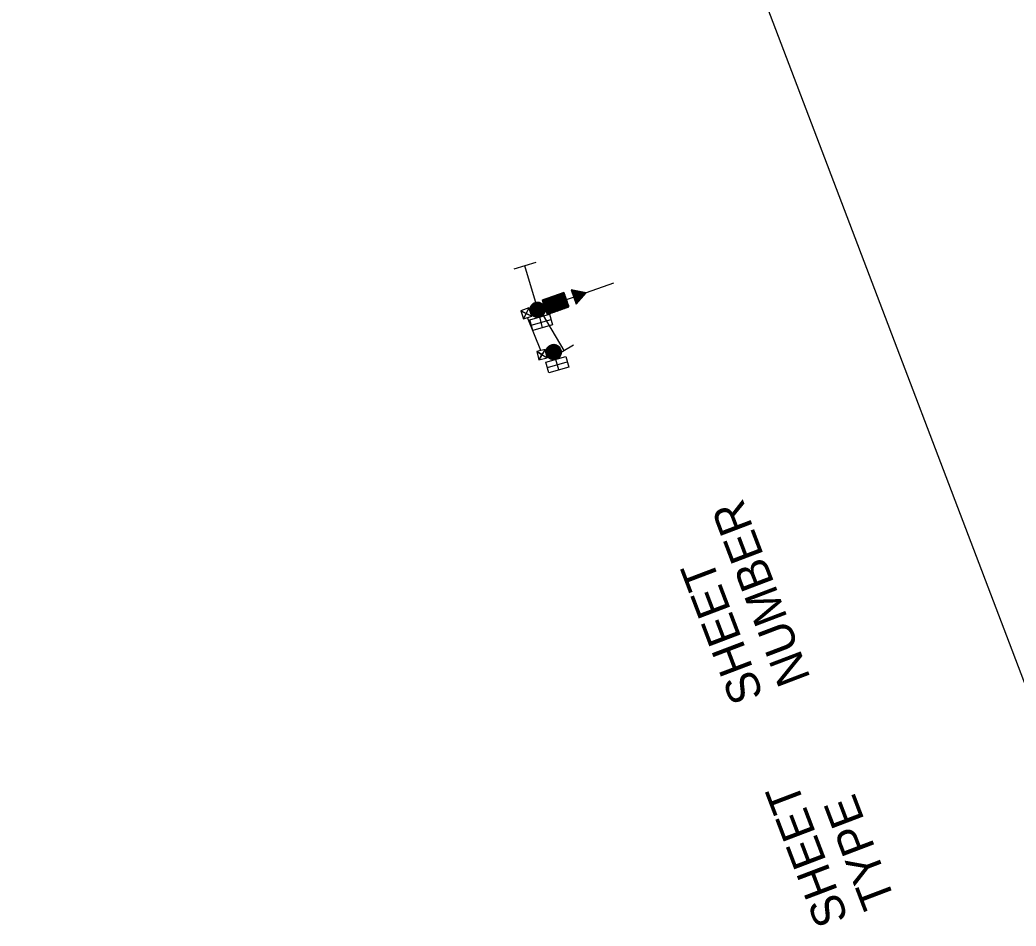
# Model space of a CAD drawing. Extents: x 601462 to 605493, y 331960 to 402715.
# Drawn here: x 601876 to 602398, y 352456 to 352931 of the extents above; entities that cross this region are included whole.
import ezdxf

# ---------------------------------------------------------------- set-up
doc = ezdxf.new("R2010")
doc.units = 0
for name, color, linetype in [('P_FTMS', 7, 'Continuous'), ('P_FTMSConduit', 7, 'Continuous'), ('P_MISC_TXT_2A (Construction)', 7, 'Continuous')]:
    doc.layers.add(name, color=color, linetype=linetype)

# ---------------------------------------------------------------- blocks, each defined once
blk = doc.blocks.new('FMB')
at = {"layer": 'P_FTMS'}
for p, q in [((24.4, -24.4), (-24.4, 24.4)), ((-24.4, -24.4), (24.4, 24.4))]:
    blk.add_line(p, q, dxfattribs=at)
blk.add_lwpolyline([(24.4, -24.4), (24.4, 24.4), (-24.4, 24.4), (-24.4, -24.4)], close=True, dxfattribs=at)
blk = doc.blocks.new('_U256')
at = {"layer": 'P_FTMS'}
for points in [[(-14.7, -7), (7, -14.7), (0, 0)], [(14.7, 7), (-7, 14.7), (0, 0)]]:
    blk.add_lwpolyline(points, close=True, dxfattribs=at)
at = {"layer": 'P_FTMS', "xscale": 0.4713263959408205, "yscale": 0.4713263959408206, "rotation": 70.39802054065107}
blk.add_blockref('FMB', (0, 0), dxfattribs=at)
blk = doc.blocks.new('FTMS_FERA')
at = {"layer": 'P_FTMS'}
for p, q in [((-65.1, 36.6), (-65.1, -36.6)), ((65.1, 0), (-65.1, 0))]:
    blk.add_line(p, q, dxfattribs=at)

msp = doc.modelspace()

# ---------------------------------------------------------------- linework, layer by layer
at = {"layer": 'P_FTMS'}
for p, q in [((602164.61, 352789.09), (602164.61, 352789.08)), ((602164.65, 352788.96), (602170.97, 352785.93)), ((602164.86, 352789.05), (602164.72, 352788.76)), ((602164.76, 352788.64), (602170.81, 352785.74)), ((602165.1, 352789), (602164.83, 352788.44)), ((602164.88, 352788.32), (602170.65, 352785.56)), ((602165.34, 352788.96), (602164.94, 352788.12)), ((602165.59, 352788.91), (602165.06, 352787.8)), ((602165.13, 352789), (602171.13, 352786.12)), ((602165.83, 352788.87), (602165.17, 352787.48)), ((602166.08, 352788.82), (602165.28, 352787.16)), ((602166.32, 352788.77), (602165.4, 352786.84)), ((602166.57, 352788.73), (602165.51, 352786.52)), ((602166.81, 352788.68), (602165.62, 352786.2)), ((602167.05, 352788.64), (602165.73, 352785.88)), ((602167.3, 352788.59), (602165.85, 352785.56)), ((602167.54, 352788.55), (602165.96, 352785.24)), ((602166.04, 352788.83), (602171.3, 352786.31)), ((602167.79, 352788.5), (602166.07, 352784.92)), ((602168.03, 352788.45), (602166.19, 352784.6)), ((602168.28, 352788.41), (602166.3, 352784.28)), ((602168.52, 352788.36), (602166.41, 352783.96)), ((602168.76, 352788.32), (602166.52, 352783.64)), ((602169.01, 352788.27), (602166.64, 352783.32)), ((602169.25, 352788.23), (602166.75, 352783)), ((602169.5, 352788.18), (602166.86, 352782.68)), ((602166.95, 352788.66), (602171.46, 352786.5)), ((602169.74, 352788.13), (602166.98, 352782.36)), ((602167.86, 352788.49), (602171.62, 352786.69)), ((602168.78, 352788.31), (602171.78, 352786.88)), ((602169.69, 352788.14), (602171.94, 352787.07)), ((602186.77, 352792.68), (602172.43, 352787.63)), ((602149.63, 352783.82), (602149.55, 352783.66)), ((602149.58, 352783.57), (602159.51, 352778.82)), ((602149.63, 352783.82), (602159.83, 352778.93)), ((602149.95, 352783.93), (602149.66, 352783.34)), ((602149.7, 352783.25), (602159.19, 352778.71)), ((602150.27, 352784.04), (602149.78, 352783.02)), ((602149.81, 352782.93), (602158.87, 352778.59)), ((602150.59, 352784.16), (602149.89, 352782.7)), ((602149.95, 352783.93), (602160.15, 352779.05)), ((602150.91, 352784.27), (602150, 352782.38)), ((602151.23, 352784.38), (602150.12, 352782.06)), ((602151.55, 352784.5), (602150.23, 352781.74)), ((602150.27, 352784.04), (602160.47, 352779.16)), ((602151.87, 352784.61), (602150.34, 352781.42)), ((602152.19, 352784.72), (602150.45, 352781.1)), ((602152.51, 352784.83), (602150.57, 352780.78)), ((602150.59, 352784.16), (602160.79, 352779.27)), ((602152.83, 352784.95), (602150.68, 352780.46)), ((602153.15, 352785.06), (602150.79, 352780.14)), ((602153.47, 352785.17), (602150.91, 352779.82)), ((602150.91, 352784.27), (602161.11, 352779.38)), ((602153.79, 352785.29), (602151.02, 352779.5)), ((602154.11, 352785.4), (602151.13, 352779.18)), ((602151.23, 352784.38), (602161.43, 352779.5)), ((602154.43, 352785.51), (602151.24, 352778.86)), ((602154.75, 352785.62), (602151.36, 352778.54)), ((602155.07, 352785.74), (602151.47, 352778.22)), ((602151.55, 352784.5), (602161.75, 352779.61)), ((602155.39, 352785.85), (602151.58, 352777.9)), ((602155.71, 352785.96), (602151.69, 352777.58)), ((602156.03, 352786.07), (602151.81, 352777.26)), ((602151.87, 352784.61), (602162.07, 352779.72)), ((602156.35, 352786.19), (602151.92, 352776.94)), ((602156.67, 352786.3), (602152.03, 352776.62)), ((602156.99, 352786.41), (602152.15, 352776.3)), ((602152.19, 352784.72), (602162.39, 352779.83)), ((602157.31, 352786.53), (602152.42, 352776.32)), ((602152.51, 352784.83), (602162.71, 352779.95)), ((602157.63, 352786.64), (602152.74, 352776.43)), ((602152.83, 352784.95), (602163.03, 352780.06)), ((602157.95, 352786.75), (602153.06, 352776.55)), ((602153.15, 352785.06), (602163.35, 352780.17)), ((602158.27, 352786.86), (602153.38, 352776.66)), ((602153.47, 352785.17), (602163.42, 352780.4)), ((602158.59, 352786.98), (602153.7, 352776.77)), ((602153.79, 352785.29), (602163.31, 352780.72)), ((602158.91, 352787.09), (602154.02, 352776.89)), ((602154.11, 352785.4), (602163.2, 352781.04)), ((602159.23, 352787.2), (602154.34, 352777)), ((602154.43, 352785.51), (602163.09, 352781.36)), ((602159.55, 352787.32), (602154.66, 352777.11)), ((602154.75, 352785.62), (602162.97, 352781.68)), ((602159.87, 352787.43), (602154.98, 352777.22)), ((602155.07, 352785.74), (602162.86, 352782)), ((602160.19, 352787.54), (602155.3, 352777.34)), ((602155.39, 352785.85), (602162.75, 352782.32)), ((602160.51, 352787.65), (602155.62, 352777.45)), ((602155.71, 352785.96), (602162.63, 352782.64)), ((602160.83, 352787.77), (602155.94, 352777.56)), ((602156.03, 352786.07), (602162.52, 352782.97)), ((602160.94, 352787.45), (602156.26, 352777.68)), ((602156.35, 352786.19), (602162.41, 352783.28)), ((602161.06, 352787.13), (602156.58, 352777.79)), ((602156.67, 352786.3), (602162.3, 352783.61)), ((602161.17, 352786.81), (602156.9, 352777.9)), ((602156.99, 352786.41), (602162.18, 352783.93)), ((602161.28, 352786.49), (602157.22, 352778.01)), ((602157.31, 352786.53), (602162.07, 352784.25)), ((602161.39, 352786.17), (602157.54, 352778.13)), ((602157.63, 352786.64), (602161.96, 352784.57)), ((602161.51, 352785.85), (602157.86, 352778.24)), ((602157.95, 352786.75), (602161.84, 352784.89)), ((602161.62, 352785.53), (602158.18, 352778.35)), ((602158.27, 352786.86), (602161.73, 352785.21)), ((602161.73, 352785.21), (602158.5, 352778.47)), ((602158.59, 352786.98), (602161.62, 352785.53)), ((602161.84, 352784.89), (602158.82, 352778.58)), ((602158.91, 352787.09), (602161.51, 352785.85)), ((602161.96, 352784.57), (602159.14, 352778.69)), ((602159.23, 352787.2), (602161.39, 352786.17)), ((602162.07, 352784.25), (602159.46, 352778.8)), ((602159.55, 352787.32), (602161.28, 352786.49)), ((602162.18, 352783.93), (602159.78, 352778.92)), ((602159.87, 352787.43), (602161.17, 352786.81)), ((602162.3, 352783.61), (602160.1, 352779.03)), ((602160.19, 352787.54), (602161.06, 352787.13)), ((602162.41, 352783.28), (602160.43, 352779.14)), ((602160.51, 352787.65), (602160.94, 352787.45)), ((602162.52, 352782.97), (602160.74, 352779.25)), ((602162.16, 352783.99), (602165.93, 352785.32)), ((602164.99, 352788), (602170.49, 352785.37)), ((602165.1, 352787.68), (602170.33, 352785.18)), ((602165.21, 352787.36), (602170.16, 352784.99)), ((602165.33, 352787.04), (602170, 352784.8)), ((602165.44, 352786.72), (602169.84, 352784.61)), ((602165.55, 352786.4), (602169.68, 352784.42)), ((602165.66, 352786.08), (602169.52, 352784.23)), ((602165.78, 352785.76), (602169.36, 352784.05)), ((602165.89, 352785.44), (602169.19, 352783.86)), ((602166, 352785.12), (602169.03, 352783.67)), ((602166.12, 352784.8), (602168.87, 352783.48)), ((602166.23, 352784.48), (602168.71, 352783.29)), ((602166.34, 352784.16), (602168.55, 352783.1)), ((602166.45, 352783.84), (602168.39, 352782.91)), ((602166.57, 352783.52), (602168.22, 352782.73)), ((602166.68, 352783.2), (602168.06, 352782.54)), ((602169.98, 352788.09), (602167.09, 352782.04)), ((602170.23, 352788.04), (602167.2, 352781.72)), ((602170.47, 352788), (602167.6, 352782)), ((602170.72, 352787.95), (602168.2, 352782.7)), ((602170.96, 352787.91), (602168.81, 352783.4)), ((602171.21, 352787.86), (602169.41, 352784.11)), ((602171.45, 352787.81), (602170.01, 352784.81)), ((602170.6, 352787.97), (602172.1, 352787.25)), ((602171.69, 352787.77), (602170.62, 352785.52)), ((602171.94, 352787.72), (602171.22, 352786.22)), ((602171.51, 352787.8), (602172.26, 352787.44)), ((602172.18, 352787.68), (602171.82, 352786.93)), ((602172.43, 352787.63), (602172.43, 352787.63)), ((602144.56, 352781.77), (602143.08, 352778.68)), ((602143.08, 352778.72), (602149.61, 352775.6)), ((602143.08, 352778.46), (602149.39, 352775.44)), ((602143.09, 352778.98), (602149.8, 352775.77)), ((602144.97, 352782.07), (602143.11, 352778.19)), ((602143.11, 352779.24), (602149.98, 352775.95)), ((602143.11, 352778.18), (602149.16, 352775.28)), ((602144.07, 352781.3), (602143.14, 352779.36)), ((602143.15, 352777.89), (602148.91, 352775.13)), ((602143.16, 352779.48), (602150.15, 352776.14)), ((602145.33, 352782.27), (602143.18, 352777.77)), ((602143.22, 352779.72), (602150.29, 352776.33)), ((602145.66, 352782.41), (602143.28, 352777.43)), ((602143.29, 352779.96), (602150.44, 352776.53)), ((602143.38, 352780.18), (602150.55, 352776.74)), ((602145.98, 352782.52), (602143.39, 352777.11)), ((602143.47, 352780.4), (602150.66, 352776.95)), ((602146.28, 352782.59), (602143.53, 352776.84)), ((602143.58, 352780.61), (602150.77, 352777.17)), ((602146.57, 352782.63), (602143.67, 352776.57)), ((602143.71, 352780.82), (602150.84, 352777.4)), ((602146.85, 352782.66), (602143.83, 352776.36)), ((602143.83, 352781.02), (602150.92, 352777.63)), ((602147.11, 352782.66), (602143.99, 352776.14)), ((602143.99, 352781.21), (602150.98, 352777.87)), ((602147.38, 352782.66), (602144.16, 352775.94)), ((602144.16, 352781.4), (602151.01, 352778.12)), ((602144.33, 352781.59), (602151.05, 352778.37)), ((602147.63, 352782.62), (602144.34, 352775.77)), ((602147.87, 352782.58), (602144.53, 352775.59)), ((602144.53, 352781.75), (602151.06, 352778.63)), ((602148.12, 352782.53), (602144.72, 352775.45)), ((602144.74, 352781.92), (602151.05, 352778.9)), ((602148.34, 352782.45), (602144.92, 352775.31)), ((602144.98, 352782.07), (602151.04, 352779.17)), ((602148.57, 352782.37), (602145.13, 352775.18)), ((602145.23, 352782.22), (602150.97, 352779.47)), ((602148.79, 352782.28), (602145.35, 352775.08)), ((602145.5, 352782.35), (602150.91, 352779.76)), ((602149, 352782.16), (602145.56, 352774.98)), ((602149.21, 352782.04), (602145.79, 352774.89)), ((602145.83, 352782.46), (602150.8, 352780.08)), ((602149.41, 352781.91), (602146.02, 352774.83)), ((602146.17, 352782.57), (602150.67, 352780.41)), ((602149.6, 352781.75), (602146.26, 352774.77)), ((602149.8, 352781.6), (602146.51, 352774.73)), ((602146.58, 352782.64), (602150.45, 352780.78)), ((602149.97, 352781.41), (602146.76, 352774.7)), ((602150.14, 352781.21), (602147.02, 352774.68)), ((602147.08, 352782.66), (602150.17, 352781.18)), ((602150.31, 352781.01), (602147.29, 352774.7)), ((602150.46, 352780.76), (602147.57, 352774.72)), ((602147.76, 352782.6), (602149.7, 352781.67)), ((602150.61, 352780.52), (602147.85, 352774.76)), ((602150.74, 352780.23), (602148.16, 352774.84)), ((602150.86, 352779.93), (602148.47, 352774.94)), ((602150.95, 352779.57), (602148.81, 352775.09)), ((602151.03, 352779.18), (602149.17, 352775.29)), ((602151.06, 352778.67), (602149.56, 352775.55)), ((602149.92, 352782.61), (602158.55, 352778.48)), ((602150.04, 352782.29), (602158.23, 352778.37)), ((602151, 352777.99), (602150.05, 352776.01)), ((602150.15, 352781.97), (602157.91, 352778.26)), ((602150.26, 352781.65), (602157.59, 352778.14)), ((602150.37, 352781.33), (602157.27, 352778.03)), ((602150.49, 352781.01), (602156.95, 352777.92)), ((602150.6, 352780.69), (602156.63, 352777.8)), ((602150.71, 352780.37), (602156.31, 352777.69)), ((602150.82, 352780.05), (602155.99, 352777.58)), ((602150.94, 352779.73), (602155.67, 352777.47)), ((602151.05, 352779.41), (602155.35, 352777.35)), ((602151.16, 352779.09), (602155.03, 352777.24)), ((602151.28, 352778.77), (602154.71, 352777.13)), ((602151.39, 352778.45), (602154.39, 352777.01)), ((602151.5, 352778.13), (602154.07, 352776.9)), ((602151.61, 352777.81), (602153.75, 352776.79)), ((602155.35, 352781.6), (602155.1, 352781.51)), ((602155.35, 352781.6), (602155.35, 352781.6)), ((602162.63, 352782.64), (602161.07, 352779.37)), ((602162.75, 352782.32), (602161.39, 352779.48)), ((602162.86, 352782), (602161.71, 352779.59)), ((602162.97, 352781.68), (602162.03, 352779.71)), ((602163.09, 352781.36), (602162.35, 352779.82)), ((602163.2, 352781.04), (602162.67, 352779.93)), ((602163.31, 352780.72), (602162.99, 352780.04)), ((602163.42, 352780.4), (602163.31, 352780.16)), ((602166.79, 352782.88), (602167.9, 352782.35)), ((602166.91, 352782.56), (602167.74, 352782.16)), ((602167.02, 352782.24), (602167.58, 352781.97)), ((602167.13, 352781.92), (602167.42, 352781.78)), ((602167.24, 352781.6), (602167.25, 352781.59)), ((602143.23, 352777.59), (602148.62, 352775.01)), ((602143.33, 352777.27), (602148.32, 352774.88)), ((602143.48, 352776.93), (602147.96, 352774.79)), ((602143.66, 352776.58), (602147.56, 352774.72)), ((602143.72, 352770.62), (602154.15, 352773.55)), ((602143.96, 352776.17), (602147.08, 352774.68)), ((602144.43, 352775.68), (602146.41, 352774.73)), ((602149.71, 352769.33), (602148.16, 352774.84)), ((602151.73, 352777.49), (602153.43, 352776.68)), ((602151.84, 352777.17), (602153.11, 352776.56)), ((602151.95, 352776.85), (602152.79, 352776.45)), ((602152.07, 352776.53), (602152.47, 352776.34)), ((602158.57, 352759.01), (602151.48, 352756.72)), ((602158.72, 352758.81), (602151.48, 352756.47)), ((602158.85, 352758.6), (602151.48, 352756.22)), ((602158.39, 352759.21), (602151.5, 352756.98)), ((602158.99, 352758.39), (602151.51, 352755.98)), ((602151.51, 352757.03), (602152.57, 352753.74)), ((602158.21, 352759.4), (602151.55, 352757.25)), ((602159.08, 352758.17), (602151.55, 352755.74)), ((602159.18, 352757.95), (602151.59, 352755.5)), ((602157.99, 352759.58), (602151.6, 352757.52)), ((602151.6, 352757.53), (602152.93, 352753.42)), ((602159.27, 352757.72), (602151.67, 352755.27)), ((602157.76, 352759.76), (602151.7, 352757.8)), ((602151.73, 352757.9), (602153.26, 352753.18)), ((602159.32, 352757.49), (602151.75, 352755.04)), ((602157.51, 352759.93), (602151.8, 352758.09)), ((602159.38, 352757.26), (602151.84, 352754.82)), ((602151.87, 352758.24), (602153.58, 352752.98)), ((602157.2, 352760.08), (602151.96, 352758.39)), ((602159.42, 352757.02), (602151.96, 352754.61)), ((602152.04, 352758.53), (602153.87, 352752.84)), ((602156.88, 352760.23), (602152.13, 352758.7)), ((602152.2, 352758.8), (602154.16, 352752.72)), ((602152.38, 352759.02), (602154.44, 352752.64)), ((602156.48, 352760.36), (602152.39, 352759.04)), ((602152.56, 352759.24), (602154.71, 352752.58)), ((602155.99, 352760.45), (602152.72, 352759.39)), ((602152.75, 352759.42), (602154.98, 352752.53)), ((602152.95, 352759.59), (602155.24, 352752.52)), ((602153.15, 352759.76), (602155.49, 352752.51)), ((602155.3, 352760.48), (602153.26, 352759.82)), ((602153.36, 352759.88), (602155.74, 352752.52)), ((602153.57, 352760.01), (602155.99, 352752.54)), ((602153.79, 352760.12), (602156.23, 352752.57)), ((602154.01, 352760.21), (602156.46, 352752.63)), ((602154.24, 352760.3), (602156.69, 352752.7)), ((602154.47, 352760.36), (602156.92, 352752.77)), ((602154.71, 352760.41), (602157.14, 352752.88)), ((602154.94, 352760.46), (602157.36, 352752.99)), ((602155.19, 352760.48), (602157.57, 352753.1)), ((602155.44, 352760.48), (602157.78, 352753.25)), ((602155.69, 352760.49), (602157.98, 352753.4)), ((602155.95, 352760.45), (602158.18, 352753.57)), ((602156.22, 352760.42), (602158.37, 352753.76)), ((602156.49, 352760.35), (602158.56, 352753.96)), ((602156.77, 352760.26), (602158.73, 352754.21)), ((602157.06, 352760.16), (602158.9, 352754.46)), ((602157.36, 352760), (602159.05, 352754.76)), ((602157.67, 352759.83), (602159.2, 352755.08)), ((602158, 352759.58), (602159.32, 352755.49)), ((602158.37, 352759.23), (602159.42, 352755.97)), ((602158.79, 352758.69), (602159.45, 352756.65)), ((602151.48, 352756.35), (602152.15, 352754.26)), ((602159.44, 352756.77), (602152.07, 352754.39)), ((602159.46, 352756.53), (602152.21, 352754.18)), ((602159.45, 352756.27), (602152.37, 352753.98)), ((602159.42, 352756.01), (602152.53, 352753.78)), ((602159.39, 352755.75), (602152.73, 352753.6)), ((602159.32, 352755.47), (602152.94, 352753.41)), ((602159.24, 352755.19), (602153.17, 352753.23)), ((602159.12, 352754.9), (602153.43, 352753.07)), ((602158.98, 352754.61), (602153.72, 352752.91)), ((602158.78, 352754.29), (602154.06, 352752.76)), ((602158.56, 352753.97), (602154.45, 352752.64)), ((602158.21, 352753.6), (602154.92, 352752.54)), ((602157.67, 352753.17), (602155.59, 352752.5)), ((602158.21, 352747.18), (602156.65, 352752.69)), ((602152.22, 352748.46), (602162.64, 352751.4))]:
    msp.add_line(p, q, dxfattribs=at)
for points in [[(602164.6, 352789.1), (602167.25, 352781.59), (602172.43, 352787.63)], [(602152.17, 352776.23), (602163.49, 352780.22), (602160.83, 352787.77), (602149.51, 352783.78)], [(602144.5, 352767.86), (602142.95, 352773.37), (602153.37, 352776.31), (602154.92, 352770.8)], [(602152.99, 352745.71), (602151.44, 352751.22), (602161.86, 352754.16), (602163.42, 352748.64)]]:
    msp.add_lwpolyline(points, close=True, dxfattribs=at)
for centre in [(602147.07, 352778.68), (602155.47, 352756.5)]:
    msp.add_circle(centre, 4, dxfattribs=at)
at = {"layer": 'P_FTMSConduit'}
msp.add_line((602148.82, 352757.36), (602141.83, 352774.62), dxfattribs=at)
at = {"layer": 'P_MISC_TXT_2A (Construction)'}
msp.add_lwpolyline([(603347.34, 352840.34), (602787.24, 354312.38), (601875.97, 353965.65), (602436.07, 352493.61)], close=True, dxfattribs=at)

# ---------------------------------------------------------------- block references
at = {"layer": 'P_FTMS'}
for name, p, xscale, yscale, rotation in [('FTMS_FERA', (602143.45, 352791.41), 0.16404166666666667, 0.16404166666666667, -73.23242705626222), ('_U256', (602141.11, 352776.76), 0.19684999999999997, 0.19685, 128.05887942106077), ('FTMS_FERA', (602155.38, 352766.48), 0.16404166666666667, 0.16404166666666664, 120.32823896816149), ('_U256', (602149.36, 352755.17), 0.19684999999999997, 0.19684999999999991, 123.4112964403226)]:
    msp.add_blockref(name, p, dxfattribs=dict(at, xscale=xscale, yscale=yscale, rotation=rotation))

# ---------------------------------------------------------------- texts
at = {"layer": 'P_MISC_TXT_2A (Construction)'}
for s, p in [('NUMBER', (602290.16, 352585.69)), ('SHEET', (602265.62, 352576.36)), ('SHEET', (602310.08, 352459.53)), ('TYPE', (602334.61, 352468.87))]:
    msp.add_text(s, height=17.5, rotation=110.8314, dxfattribs=at).set_placement(p)

doc.saveas('drawing.dxf')
